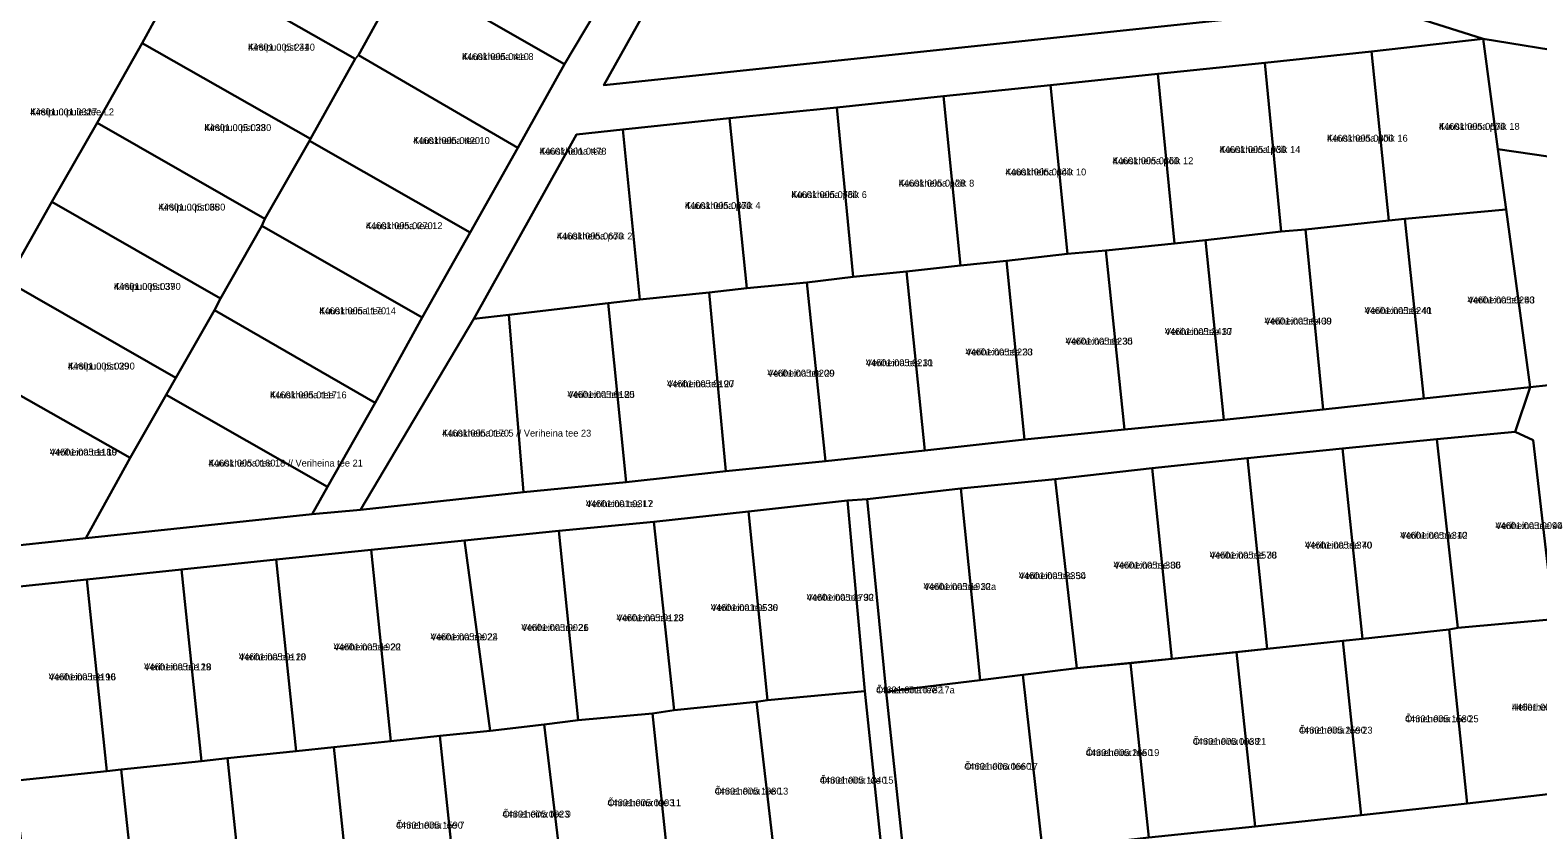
# Model space of a CAD drawing. Extents: x 551843 to 558501, y 6589003 to 6595718.
# Drawn here: x 552683 to 553010, y 6593014.7 to 6593188.1 of the extents above; entities that cross this region are included whole.
import ezdxf

# ---------------------------------------------------------------- set-up
doc = ezdxf.new("R2010")
doc.units = 0
for name, color, linetype in [('L_AADRESS', 7, 'Continuous'), ('PIIR', 7, 'Continuous'), ('TUNNUS', 7, 'Continuous')]:
    doc.layers.add(name, color=color, linetype=linetype)

msp = doc.modelspace()

# ---------------------------------------------------------------- linework, layer by layer
at = {"layer": 'PIIR'}
for points in [[(552840.87, 6593236.09), (552807.46, 6593176.14), (552974.33, 6593193.77), (552998.09, 6593186.23), (552973.9, 6593183.46), (552950.79, 6593181.04), (552927.56, 6593178.6), (552904.3, 6593176.17), (552881.06, 6593173.77), (552857.92, 6593171.33), (552834.69, 6593168.99), (552811.53, 6593166.52), (552801.5, 6593165.46), (552779.22, 6593125.49), (552754.69, 6593084.09), (552744.18, 6593083.16), (552747.49, 6593089.07), (552757.85, 6593107.29), (552768.05, 6593125.79), (552778.43, 6593144.18), (552788.77, 6593162.59), (552798.93, 6593180.69), (552809.88, 6593199.24)], [(552716.86, 6593202.78), (552707.32, 6593185.27), (552697.57, 6593168.03), (552687.74, 6593150.83), (552678.02, 6593133.63), (552668.08, 6593116.1), (552645.42, 6593075.5), (552646.4, 6593072.72), (552635.11, 6593058.59), (552633.88, 6593058.47), (552621.46, 6593064.96), (552611.39, 6593070.23), (552615.82, 6593077.03), (552635.65, 6593111.86), (552655.45, 6593146.62), (552659.45, 6593154.58), (552669.58, 6593173.09), (552679.92, 6593191.28)], [(553210.5, 6593154.04), (553185.99, 6593153.35), (553168.36, 6593153.21), (553161.52, 6593154.87), (553162.16, 6593163.31), (553155.5, 6593163.81), (553154.89, 6593155.73), (553153.63, 6593155.37), (553133.98, 6593158.48), (553114.18, 6593161.25), (553095.28, 6593164.17), (553075.92, 6593167.19), (553055.93, 6593169.86), (553040.97, 6593172.32), (553030.99, 6593177.02), (553018.59, 6593182.86), (552998.09, 6593186.23), (552974.33, 6593193.77)], [(552673.25, 6593075.58), (552695.08, 6593077.94), (552744.18, 6593083.16), (552754.69, 6593084.09), (552790.04, 6593087.88), (552812.24, 6593090.07), (552833.91, 6593092.44), (552855.53, 6593094.63), (552877.01, 6593096.97), (552898.63, 6593099.35), (552920.34, 6593101.5), (552941.85, 6593103.56), (552963.44, 6593105.82), (552985.23, 6593108.24), (553008.31, 6593110.7), (553005.02, 6593100.97), (552988.08, 6593099.36), (552967.63, 6593097.4), (552946.97, 6593095.26), (552926.31, 6593093.1), (552905.31, 6593090.73), (552884.84, 6593088.66), (552864.54, 6593086.35), (552860.28, 6593086.08), (552838.8, 6593083.72), (552818.28, 6593081.43), (552797.67, 6593079.48), (552777.19, 6593077.45), (552756.95, 6593075.41), (552736.4, 6593073.26), (552715.85, 6593071.11), (552695.3, 6593068.96), (552674.47, 6593066.79)], [(553013.43, 6593060.38), (553008.91, 6593099.16), (553005.02, 6593100.97), (553008.31, 6593110.7), (553012.28, 6593111.12)], [(552679.49, 6593025.29), (552684.04, 6592987.57), (552706.79, 6592989.96), (552729.82, 6592992.39), (552752.85, 6592994.82), (552775.88, 6592997.25), (552799.02, 6592999.56), (552821.94, 6593002.1), (552844.97, 6593004.53), (552868.01, 6593006.97), (552872.65, 6593007.42), (552902.53, 6593010.35), (552925.6, 6593012.99), (552948.63, 6593015.42), (552971.67, 6593017.86), (552994.64, 6593020.4), (553017.86, 6593023.03)]]:
    msp.add_lwpolyline(points, dxfattribs=at)
for points in [[(552807.46, 6593176.14), (552840.87, 6593236.09), (552974.33, 6593193.77)], [(552763.13, 6593198.84), (552754.26, 6593182.64), (552753.54, 6593181.86), (552716.86, 6593202.78), (552726.95, 6593219.7)], [(552772.92, 6593216.16), (552774.63, 6593219.35), (552809.88, 6593199.24), (552798.93, 6593180.69), (552764.24, 6593200.63)], [(552716.86, 6593202.78), (552753.54, 6593181.86), (552743.84, 6593164.53), (552707.32, 6593185.27)], [(552763.13, 6593198.84), (552764.24, 6593200.63), (552798.93, 6593180.69), (552788.77, 6593162.59), (552754.26, 6593182.64)], [(552981.12, 6593147.15), (552977.68, 6593146.79), (552973.9, 6593183.46), (552998.09, 6593186.23), (553001.28, 6593162.32), (553003.1, 6593149.18)], [(553030.99, 6593177.02), (553027.1, 6593158.56), (553001.28, 6593162.32), (552998.09, 6593186.23), (553018.59, 6593182.86)], [(552707.32, 6593185.27), (552743.84, 6593164.53), (552743.61, 6593164.09), (552733.91, 6593147.15), (552697.57, 6593168.03)], [(552743.84, 6593164.53), (552753.54, 6593181.86), (552754.26, 6593182.64), (552788.77, 6593162.59), (552778.43, 6593144.18), (552743.61, 6593164.09)], [(552954.33, 6593144.44), (552950.79, 6593181.04), (552973.9, 6593183.46), (552977.68, 6593146.79), (552959.56, 6593144.89)], [(552927.56, 6593178.6), (552950.79, 6593181.04), (552954.33, 6593144.44), (552937.92, 6593142.58), (552931.18, 6593141.82)], [(552881.06, 6593173.77), (552904.3, 6593176.17), (552907.97, 6593139.59), (552894.74, 6593138.05), (552884.79, 6593137.04)], [(552927.56, 6593178.6), (552931.18, 6593141.82), (552916.31, 6593140.34), (552907.97, 6593139.59), (552904.3, 6593176.17)], [(552857.92, 6593171.33), (552881.06, 6593173.77), (552884.79, 6593137.04), (552873.08, 6593135.77), (552861.48, 6593134.57)], [(552861.48, 6593134.57), (552851.46, 6593133.34), (552838.46, 6593132.14), (552834.69, 6593168.99), (552857.92, 6593171.33)], [(552697.57, 6593168.03), (552733.91, 6593147.15), (552733.28, 6593145.66), (552724.34, 6593129.93), (552687.74, 6593150.83)], [(552779.22, 6593125.49), (552801.5, 6593165.46), (552811.53, 6593166.52), (552815.24, 6593129.66), (552808.34, 6593128.89), (552786.84, 6593126.38)], [(552834.69, 6593168.99), (552838.46, 6593132.14), (552830.25, 6593131.22), (552815.24, 6593129.66), (552811.53, 6593166.52)], [(552733.91, 6593147.15), (552743.61, 6593164.09), (552778.43, 6593144.18), (552768.05, 6593125.79), (552733.28, 6593145.66)], [(553003.1, 6593149.18), (553001.28, 6593162.32), (553027.1, 6593158.56), (553012.28, 6593111.12), (553008.31, 6593110.7)], [(552687.74, 6593150.83), (552724.34, 6593129.93), (552722.99, 6593127.4), (552714.66, 6593112.72), (552678.02, 6593133.63)], [(552959.56, 6593144.89), (552977.68, 6593146.79), (552981.12, 6593147.15), (552985.23, 6593108.24), (552963.44, 6593105.82)], [(553003.1, 6593149.18), (553008.31, 6593110.7), (552985.23, 6593108.24), (552981.12, 6593147.15)], [(552768.05, 6593125.79), (552757.85, 6593107.29), (552722.99, 6593127.4), (552724.34, 6593129.93), (552733.28, 6593145.66)], [(552954.33, 6593144.44), (552959.56, 6593144.89), (552963.44, 6593105.82), (552941.85, 6593103.56), (552937.92, 6593142.58)], [(552894.74, 6593138.05), (552907.97, 6593139.59), (552916.31, 6593140.34), (552920.34, 6593101.5), (552898.63, 6593099.35)], [(552916.31, 6593140.34), (552931.18, 6593141.82), (552937.92, 6593142.58), (552941.85, 6593103.56), (552920.34, 6593101.5)], [(552873.08, 6593135.77), (552884.79, 6593137.04), (552894.74, 6593138.05), (552898.63, 6593099.35), (552877.01, 6593096.97)], [(552678.02, 6593133.63), (552714.66, 6593112.72), (552712.54, 6593108.99), (552704.72, 6593095.37), (552668.08, 6593116.1)], [(552851.46, 6593133.34), (552861.48, 6593134.57), (552873.08, 6593135.77), (552877.01, 6593096.97), (552855.53, 6593094.63)], [(552808.34, 6593128.89), (552815.24, 6593129.66), (552830.25, 6593131.22), (552833.91, 6593092.44), (552812.24, 6593090.07)], [(552830.25, 6593131.22), (552838.46, 6593132.14), (552851.46, 6593133.34), (552855.53, 6593094.63), (552833.91, 6593092.44)], [(552747.49, 6593089.07), (552712.54, 6593108.99), (552714.66, 6593112.72), (552722.99, 6593127.4), (552757.85, 6593107.29)], [(552786.84, 6593126.38), (552808.34, 6593128.89), (552812.24, 6593090.07), (552790.04, 6593087.88)], [(552779.22, 6593125.49), (552786.84, 6593126.38), (552790.04, 6593087.88), (552754.69, 6593084.09)], [(552704.72, 6593095.37), (552695.08, 6593077.94), (552673.25, 6593075.58), (552668.08, 6593116.1)], [(552704.72, 6593095.37), (552712.54, 6593108.99), (552747.49, 6593089.07), (552744.18, 6593083.16), (552695.08, 6593077.94)], [(553005.02, 6593100.97), (553008.91, 6593099.16), (553013.43, 6593060.38), (552992.62, 6593058.48), (552988.08, 6593099.36)], [(552988.08, 6593099.36), (552992.62, 6593058.48), (552990.74, 6593058.12), (552971.95, 6593056.12), (552967.63, 6593097.4)], [(552926.31, 6593093.1), (552946.97, 6593095.26), (552951.27, 6593053.91), (552930.62, 6593051.73)], [(552967.63, 6593097.4), (552971.95, 6593056.12), (552967.68, 6593055.65), (552951.27, 6593053.91), (552946.97, 6593095.26)], [(552905.31, 6593090.73), (552926.31, 6593093.1), (552930.62, 6593051.73), (552909.97, 6593049.72)], [(552884.84, 6593088.66), (552889, 6593047.11), (552875.32, 6593045.45), (552868.67, 6593044.62), (552864.54, 6593086.35)], [(552905.31, 6593090.73), (552909.97, 6593049.72), (552898.25, 6593048.26), (552889, 6593047.11), (552884.84, 6593088.66)], [(552838.8, 6593083.72), (552860.28, 6593086.08), (552864.03, 6593044.71), (552842.95, 6593042.82)], [(552868.67, 6593044.62), (552872.65, 6593007.42), (552868.01, 6593006.97), (552864.03, 6593044.71), (552860.28, 6593086.08), (552864.54, 6593086.35)], [(552801.88, 6593038.42), (552797.67, 6593079.48), (552818.28, 6593081.43), (552822.69, 6593040.64), (552817.95, 6593039.9)], [(552822.69, 6593040.64), (552818.28, 6593081.43), (552838.8, 6593083.72), (552842.95, 6593042.82), (552840.55, 6593042.43)], [(552797.67, 6593079.48), (552801.88, 6593038.42), (552794.49, 6593037.53), (552782.75, 6593036.13), (552777.19, 6593077.45)], [(552740.73, 6593031.75), (552736.4, 6593073.26), (552756.95, 6593075.41), (552761.27, 6593033.92), (552748.86, 6593032.61)], [(552756.95, 6593075.41), (552777.19, 6593077.45), (552782.75, 6593036.13), (552771.89, 6593035.04), (552761.27, 6593033.92)], [(552720.18, 6593029.58), (552715.85, 6593071.11), (552736.4, 6593073.26), (552740.73, 6593031.75), (552725.83, 6593030.18)], [(552674.47, 6593066.79), (552695.3, 6593068.96), (552699.64, 6593027.41), (552679.49, 6593025.29)], [(552699.64, 6593027.41), (552695.3, 6593068.96), (552715.85, 6593071.11), (552720.18, 6593029.58), (552702.8, 6593027.74)], [(553017.86, 6593023.03), (552994.64, 6593020.4), (552990.74, 6593058.12), (552992.62, 6593058.48), (553013.43, 6593060.38)], [(552944.64, 6593053.21), (552951.27, 6593053.91), (552967.68, 6593055.65), (552971.67, 6593017.86), (552948.63, 6593015.42)], [(552971.95, 6593056.12), (552990.74, 6593058.12), (552994.64, 6593020.4), (552971.67, 6593017.86), (552967.68, 6593055.65)], [(552930.62, 6593051.73), (552944.64, 6593053.21), (552948.63, 6593015.42), (552925.6, 6593012.99), (552921.61, 6593050.78)], [(552898.25, 6593048.26), (552909.97, 6593049.72), (552921.61, 6593050.78), (552925.6, 6593012.99), (552902.53, 6593010.35)], [(552898.25, 6593048.26), (552902.53, 6593010.35), (552872.65, 6593007.42), (552868.67, 6593044.62), (552875.32, 6593045.45), (552889, 6593047.11)], [(552817.95, 6593039.9), (552822.69, 6593040.64), (552840.55, 6593042.43), (552844.97, 6593004.53), (552821.94, 6593002.1)], [(552840.55, 6593042.43), (552842.95, 6593042.82), (552864.03, 6593044.71), (552868.01, 6593006.97), (552844.97, 6593004.53)], [(552801.88, 6593038.42), (552817.95, 6593039.9), (552821.94, 6593002.1), (552799.02, 6592999.56), (552794.49, 6593037.53)], [(552782.75, 6593036.13), (552794.49, 6593037.53), (552799.02, 6592999.56), (552775.88, 6592997.25), (552771.89, 6593035.04)], [(552725.83, 6593030.18), (552740.73, 6593031.75), (552748.86, 6593032.61), (552752.85, 6592994.82), (552729.82, 6592992.39)], [(552748.86, 6593032.61), (552761.27, 6593033.92), (552771.89, 6593035.04), (552775.88, 6592997.25), (552752.85, 6592994.82)], [(552702.8, 6593027.74), (552720.18, 6593029.58), (552725.83, 6593030.18), (552729.82, 6592992.39), (552706.79, 6592989.96)], [(552684.04, 6592987.57), (552679.49, 6593025.29), (552699.64, 6593027.41), (552702.8, 6593027.74), (552706.79, 6592989.96)]]:
    msp.add_lwpolyline(points, close=True, dxfattribs=at)

# ---------------------------------------------------------------- texts
at = {"layer": 'L_AADRESS'}
for s, p in [('Kirsipuu pst 31', (552730.28, 6593183.66)), ('Kuuskheina tee 8', (552776.68, 6593181.61)), ('Kirsipuu puiestee L2', (552683.05, 6593169.61)), ('Kirsipuu pst 33', (552720.81, 6593166.21)), ('Kuuskheina põik 18', (552988.5, 6593166.48)), ('Kuuskheina tee 10', (552766.08, 6593163.41)), ('Kuuskheina põik 14', (552940.95, 6593161.46)), ('Kuuskheina põik 16', (552964.23, 6593163.91)), ('Kuuskheina tee', (552793.5, 6593161.09)), ('Kuuskheina põik 12', (552917.74, 6593159.03)), ('Kuuskheina põik 10', (552894.52, 6593156.59)), ('Kuuskheina põik 6', (552848.08, 6593151.68)), ('Kuuskheina põik 8', (552871.36, 6593154.17)), ('Kirsipuu pst 35', (552710.85, 6593148.98)), ('Kuuskheina põik 4', (552825, 6593149.31)), ('Kuuskheina tee 12', (552755.82, 6593144.94)), ('Kuuskheina põik 2', (552797.23, 6593142.7)), ('Kirsipuu pst 37', (552701.19, 6593131.77)), ('Veriheina tee 43', (552994.71, 6593128.83)), ('Kuuskheina tee 14', (552745.72, 6593126.48)), ('Veriheina tee 41', (552972.39, 6593126.53)), ('Veriheina tee 39', (552950.68, 6593124.26)), ('Veriheina tee 35', (552907.54, 6593119.89)), ('Veriheina tee 37', (552929.08, 6593121.97)), ('Veriheina tee 33', (552885.86, 6593117.55)), ('Kirsipuu pst 39', (552691.22, 6593114.5)), ('Veriheina tee 29', (552842.89, 6593112.95)), ('Veriheina tee 31', (552864.23, 6593115.22)), ('Veriheina tee 27', (552821.12, 6593110.66)), ('Kuuskheina tee 16', (552735.04, 6593108.24)), ('Veriheina tee 25', (552799.54, 6593108.34)), ('Kuuskheina tee 5 // Veriheina tee 23', (552772.36, 6593099.95)), ('Veriheina tee 19', (552687.28, 6593095.84)), ('Kuuskheina tee 18 // Veriheina tee 21', (552721.72, 6593093.46)), ('Veriheina tee L2', (552803.54, 6593084.65)), ('Veriheina tee 44', (553000.75, 6593079.89)), ('Veriheina tee 42', (552980.12, 6593077.79)), ('Veriheina tee 38', (552938.79, 6593073.5)), ('Veriheina tee 40', (552959.46, 6593075.67)), ('Veriheina tee 36', (552917.96, 6593071.33)), ('Veriheina tee 32a', (552876.77, 6593066.68)), ('Veriheina tee 34', (552897.41, 6593069.04)), ('Veriheina tee 32', (552851.41, 6593064.34)), ('Veriheina tee 30', (552830.62, 6593062.12)), ('Veriheina tee 26', (552789.54, 6593057.81)), ('Veriheina tee 28', (552810.18, 6593059.92)), ('Veriheina tee 22', (552748.84, 6593053.58)), ('Veriheina tee 24', (552769.85, 6593055.77)), ('Veriheina tee 20', (552728.29, 6593051.43)), ('Veriheina tee 16', (552687.05, 6593047.09)), ('Veriheina tee 18', (552707.74, 6593049.26)), ('Õnneheina tee 17a', (552866.46, 6593044.26)), ('Hellerheina tee 60', (553004.3, 6593040.52)), ('Õnneheina tee 25', (552981.16, 6593038)), ('Õnneheina tee 23', (552958.16, 6593035.53)), ('Õnneheina tee 19', (552911.93, 6593030.66)), ('Õnneheina tee 21', (552935.12, 6593033.1)), ('Õnneheina tee 17', (552885.6, 6593027.69)), ('Õnneheina tee 15', (552854.28, 6593024.68)), ('Õnneheina tee 13', (552831.46, 6593022.31)), ('Õnneheina tee 9', (552785.46, 6593017.33)), ('Õnneheina tee 11', (552808.21, 6593019.79)), ('Õnneheina tee 7', (552762.37, 6593014.93))]:
    msp.add_text(s, height=1.5, dxfattribs=at).set_placement(p)
at = {"layer": 'TUNNUS'}
for s, p in [('44601:005:2440', (552730.28, 6593183.66)), ('44601:005:0410', (552776.68, 6593181.61)), ('44601:001:0327', (552683.05, 6593169.61)), ('44601:005:0280', (552720.81, 6593166.21)), ('44601:005:0570', (552988.5, 6593166.48)), ('44601:005:0420', (552766.08, 6593163.41)), ('44601:005:1930', (552940.95, 6593161.46)), ('44601:005:0300', (552964.23, 6593163.91)), ('44601:001:0478', (552793.5, 6593161.09)), ('44601:005:0360', (552917.74, 6593159.03)), ('44601:005:0340', (552894.52, 6593156.59)), ('44601:005:0780', (552848.08, 6593151.68)), ('44601:005:0128', (552871.36, 6593154.17)), ('44601:005:0680', (552710.85, 6593148.98)), ('44601:005:0370', (552825, 6593149.31)), ('44601:005:0270', (552755.82, 6593144.94)), ('44601:005:0670', (552797.23, 6593142.7)), ('44601:005:0390', (552701.19, 6593131.77)), ('44601:005:0250', (552994.71, 6593128.83)), ('44601:005:1170', (552745.72, 6593126.48)), ('44601:005:0240', (552972.39, 6593126.53)), ('44601:005:0400', (552950.68, 6593124.26)), ('44601:005:0230', (552907.54, 6593119.89)), ('44601:005:2410', (552929.08, 6593121.97)), ('44601:005:0220', (552885.86, 6593117.55)), ('44601:005:0290', (552691.22, 6593114.5)), ('44601:005:0200', (552842.89, 6593112.95)), ('44601:005:0210', (552864.23, 6593115.22)), ('44601:005:0190', (552821.12, 6593110.66)), ('44601:005:0117', (552735.04, 6593108.24)), ('44601:005:0180', (552799.54, 6593108.34)), ('44601:005:0170', (552772.36, 6593099.95)), ('44601:005:1180', (552687.28, 6593095.84)), ('44601:005:0160', (552721.72, 6593093.46)), ('44601:001:0317', (552803.54, 6593084.65)), ('44601:005:0090', (553000.75, 6593079.89)), ('44601:005:1310', (552980.12, 6593077.79)), ('44601:005:2570', (552938.79, 6593073.5)), ('44601:005:1370', (552959.46, 6593075.67)), ('44601:005:1380', (552917.96, 6593071.33)), ('44601:005:1910', (552876.77, 6593066.68)), ('44601:005:2350', (552897.41, 6593069.04)), ('44601:005:2790', (552851.41, 6593064.34)), ('44601:001:0536', (552830.62, 6593062.12)), ('44601:005:0021', (552789.54, 6593057.81)), ('44601:005:0113', (552810.18, 6593059.92)), ('44601:005:1920', (552748.84, 6593053.58)), ('44601:005:0022', (552769.85, 6593055.77)), ('44601:005:0118', (552728.29, 6593051.43)), ('44601:005:2190', (552687.05, 6593047.09)), ('44601:005:0129', (552707.74, 6593049.26)), ('44601:001:0782', (552866.46, 6593044.26)), ('44601:005:0019', (553004.3, 6593040.52)), ('44601:005:1580', (552981.16, 6593038)), ('44601:005:2590', (552958.16, 6593035.53)), ('44601:005:2650', (552911.93, 6593030.66)), ('44601:005:0038', (552935.12, 6593033.1)), ('44601:005:0660', (552885.6, 6593027.69)), ('44601:005:1340', (552854.28, 6593024.68)), ('44601:005:1980', (552831.46, 6593022.31)), ('44601:005:0003', (552808.21, 6593019.79)), ('44601:005:1590', (552762.37, 6593014.93)), ('44601:005:0023', (552785.46, 6593017.33))]:
    msp.add_text(s, height=1.5, dxfattribs=at).set_placement(p)

doc.saveas('drawing.dxf')
